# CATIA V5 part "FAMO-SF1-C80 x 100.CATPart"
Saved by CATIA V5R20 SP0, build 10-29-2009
Part number: FAMO-SF1-C80 x 100
Definition: NONE
Nomenclature: FAMO-SF1-C80 x 100
Source: Unknown
Description: FAMO-SF1-C80 x 100
Bounding box of the stored display mesh (mm): x -52 to 48, y -55.5 to 55.5, z -55.5 to 55.5
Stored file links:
  C:\Users\Utente\Desktop\IO LAVORO\3D X SITO CF\X SITO\FAMO\FAMO-SF1-C80 x 100.CATPart
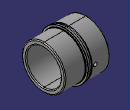
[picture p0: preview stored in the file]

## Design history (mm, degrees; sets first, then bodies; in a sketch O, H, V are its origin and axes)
Body1 "FAMO-SF1-C80 x 100" (main body)
  Solid1: solid without history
